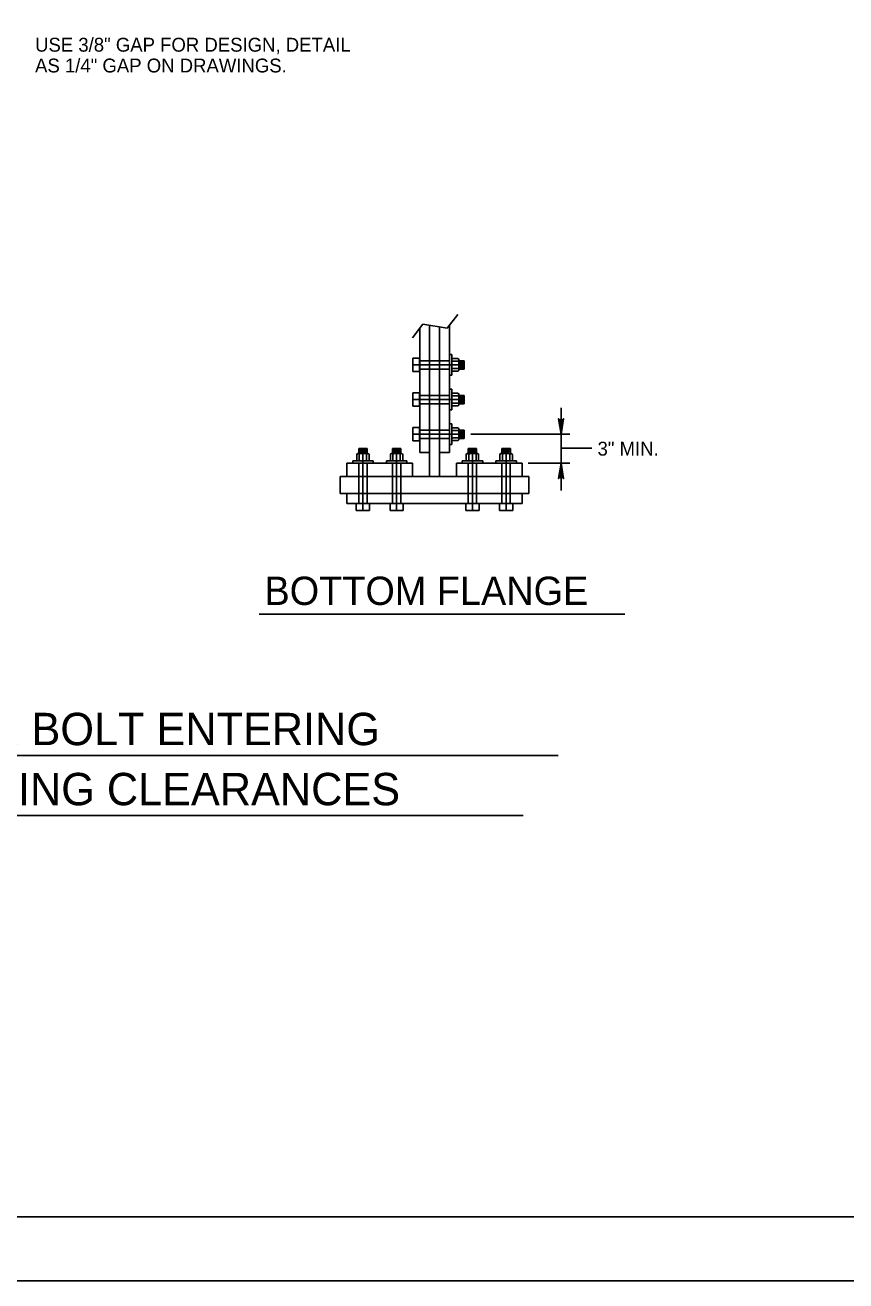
# Model space of a CAD drawing. Extents: x 638466 to 639375, y 297808 to 298996.
# Drawn here: x 638651.7 to 638843.6, y 297808.5 to 298101.9 of the extents above; entities that cross this region are included whole.
import ezdxf

# ---------------------------------------------------------------- set-up
doc = ezdxf.new("R2010")
doc.units = 0
for name, color, linetype in [('1', 7, 'Continuous'), ('2', 7, 'Continuous'), ('4', 7, 'Continuous'), ('PLT-BNDY', 7, 'Continuous')]:
    doc.layers.add(name, color=color, linetype=linetype)

msp = doc.modelspace()

# ---------------------------------------------------------------- linework, layer by layer
at = {"layer": '1'}
for p, q in [((638750.89, 298024.88), (638750.89, 298020.09)), ((638751.43, 298024.88), (638750.89, 298024.88)), ((638751.43, 298024.88), (638751.43, 298020.09)), ((638742.32, 298020.94), (638742.32, 298024.03)), ((638743.93, 298024.03), (638742.32, 298024.03)), ((638742.32, 298022.48), (638754.06, 298022.48)), ((638743.93, 298020.94), (638743.93, 298024.03)), ((638743.94, 298023.46), (638750.89, 298023.46)), ((638752.84, 298023.94), (638751.43, 298023.94)), ((638752.84, 298023.35), (638751.43, 298023.35)), ((638753.11, 298023.7), (638753.11, 298021.27)), ((638754.31, 298023.46), (638753.11, 298023.46)), ((638753.38, 298023.23), (638753.38, 298021.74)), ((638753.65, 298023.46), (638753.65, 298021.5)), ((638753.92, 298023.23), (638753.92, 298021.74)), ((638754.19, 298023.46), (638754.19, 298021.5)), ((638754.31, 298023.46), (638754.31, 298021.5)), ((638743.93, 298020.94), (638742.32, 298020.94)), ((638743.94, 298021.5), (638750.89, 298021.5)), ((638751.43, 298020.09), (638750.89, 298020.09)), ((638752.84, 298021.62), (638751.43, 298021.62)), ((638752.84, 298021.03), (638751.43, 298021.03)), ((638754.31, 298021.5), (638753.11, 298021.5)), ((638750.89, 298016.78), (638750.89, 298011.99)), ((638751.43, 298016.78), (638750.89, 298016.78)), ((638751.43, 298016.78), (638751.43, 298011.99)), ((638742.32, 298012.84), (638742.32, 298015.93)), ((638743.93, 298015.93), (638742.32, 298015.93)), ((638742.32, 298014.38), (638754.06, 298014.38)), ((638743.93, 298012.84), (638743.93, 298015.93)), ((638743.94, 298015.36), (638750.89, 298015.36)), ((638743.94, 298013.4), (638750.89, 298013.4)), ((638752.84, 298015.84), (638751.43, 298015.84)), ((638752.84, 298015.25), (638751.43, 298015.25)), ((638752.84, 298013.52), (638751.43, 298013.52)), ((638753.11, 298015.6), (638753.11, 298013.17)), ((638754.31, 298015.36), (638753.11, 298015.36)), ((638754.31, 298013.4), (638753.11, 298013.4)), ((638753.38, 298015.13), (638753.38, 298013.64)), ((638753.65, 298015.36), (638753.65, 298013.4)), ((638753.92, 298015.13), (638753.92, 298013.64)), ((638754.19, 298015.36), (638754.19, 298013.4)), ((638754.31, 298015.36), (638754.31, 298013.4)), ((638743.93, 298012.84), (638742.32, 298012.84)), ((638751.43, 298011.99), (638750.89, 298011.99)), ((638752.84, 298012.93), (638751.43, 298012.93)), ((638742.32, 298004.74), (638742.32, 298007.83)), ((638743.93, 298007.83), (638742.32, 298007.83)), ((638743.93, 298004.74), (638743.93, 298007.83)), ((638750.89, 298008.68), (638750.89, 298003.89)), ((638751.43, 298008.68), (638750.89, 298008.68)), ((638751.43, 298008.68), (638751.43, 298003.89)), ((638752.84, 298007.74), (638751.43, 298007.74)), ((638753.11, 298007.5), (638753.11, 298005.07)), ((638742.32, 298006.28), (638754.06, 298006.28)), ((638743.93, 298004.74), (638742.32, 298004.74)), ((638743.94, 298007.26), (638750.89, 298007.26)), ((638743.94, 298005.3), (638750.89, 298005.3)), ((638752.84, 298007.15), (638751.43, 298007.15)), ((638752.84, 298005.42), (638751.43, 298005.42)), ((638752.84, 298004.83), (638751.43, 298004.83)), ((638754.31, 298007.26), (638753.11, 298007.26)), ((638754.31, 298005.3), (638753.11, 298005.3)), ((638753.38, 298007.03), (638753.38, 298005.54)), ((638753.65, 298007.26), (638753.65, 298005.3)), ((638753.92, 298007.03), (638753.92, 298005.54)), ((638754.19, 298007.26), (638754.19, 298005.3)), ((638754.31, 298007.26), (638754.31, 298005.3)), ((638729.22, 298001.48), (638729.22, 298000.07)), ((638729.46, 298001.75), (638731.89, 298001.75)), ((638729.69, 298002.95), (638729.69, 298001.75)), ((638729.69, 298002.95), (638731.66, 298002.95)), ((638729.69, 298002.83), (638731.66, 298002.83)), ((638729.69, 298002.29), (638731.66, 298002.29)), ((638729.81, 298001.48), (638729.81, 298000.07)), ((638729.93, 298002.56), (638731.42, 298002.56)), ((638729.93, 298002.02), (638731.42, 298002.02)), ((638730.68, 297988.47), (638730.68, 298002.7)), ((638731.54, 298001.48), (638731.54, 298000.07)), ((638731.66, 298002.95), (638731.66, 298001.75)), ((638732.13, 298001.48), (638732.13, 298000.07)), ((638737.1, 298001.48), (638737.1, 298000.07)), ((638737.33, 298001.75), (638739.77, 298001.75)), ((638737.57, 298002.95), (638737.57, 298001.75)), ((638737.57, 298002.95), (638739.53, 298002.95)), ((638737.57, 298002.83), (638739.53, 298002.83)), ((638737.57, 298002.29), (638739.53, 298002.29)), ((638737.69, 298001.48), (638737.69, 298000.07)), ((638737.8, 298002.56), (638739.3, 298002.56)), ((638737.8, 298002.02), (638739.3, 298002.02)), ((638738.55, 297988.47), (638738.55, 298002.7)), ((638739.41, 298001.48), (638739.41, 298000.07)), ((638739.53, 298002.95), (638739.53, 298001.75)), ((638740, 298001.48), (638740, 298000.07)), ((638751.43, 298003.89), (638750.89, 298003.89)), ((638754.82, 298001.48), (638754.82, 298000.07)), ((638755.05, 298001.75), (638757.49, 298001.75)), ((638755.29, 298002.95), (638755.29, 298001.75)), ((638755.29, 298002.95), (638757.25, 298002.95)), ((638755.29, 298002.83), (638757.25, 298002.83)), ((638755.29, 298002.29), (638757.25, 298002.29)), ((638755.41, 298001.48), (638755.41, 298000.07)), ((638755.53, 298002.56), (638757.02, 298002.56)), ((638755.53, 298002.02), (638757.02, 298002.02)), ((638756.27, 297988.47), (638756.27, 298002.7)), ((638757.14, 298001.48), (638757.14, 298000.07)), ((638757.25, 298002.95), (638757.25, 298001.75)), ((638757.72, 298001.48), (638757.72, 298000.07)), ((638762.69, 298001.48), (638762.69, 298000.07)), ((638762.93, 298001.75), (638765.36, 298001.75)), ((638763.17, 298002.95), (638763.17, 298001.75)), ((638763.17, 298002.95), (638765.13, 298002.95)), ((638763.17, 298002.83), (638765.13, 298002.83)), ((638763.17, 298002.29), (638765.13, 298002.29)), ((638763.28, 298001.48), (638763.28, 298000.07)), ((638763.4, 298002.56), (638764.89, 298002.56)), ((638763.4, 298002.02), (638764.89, 298002.02)), ((638764.15, 297988.47), (638764.15, 298002.7)), ((638765.01, 298001.48), (638765.01, 298000.07)), ((638765.13, 298002.95), (638765.13, 298001.75)), ((638765.6, 298001.48), (638765.6, 298000.07)), ((638728.28, 298000.07), (638733.07, 298000.07)), ((638728.28, 298000.07), (638728.28, 297999.53)), ((638728.28, 297999.53), (638733.07, 297999.53)), ((638729.7, 297990.08), (638729.7, 297999.53)), ((638731.65, 297990.08), (638731.65, 297999.53)), ((638733.07, 298000.07), (638733.07, 297999.53)), ((638736.16, 298000.07), (638740.95, 298000.07)), ((638736.16, 298000.07), (638736.16, 297999.53)), ((638736.16, 297999.53), (638740.95, 297999.53)), ((638737.57, 297990.08), (638737.57, 297999.53)), ((638739.53, 297990.08), (638739.53, 297999.53)), ((638740.95, 298000.07), (638740.95, 297999.53)), ((638753.88, 298000.07), (638758.67, 298000.07)), ((638753.88, 298000.07), (638753.88, 297999.53)), ((638753.88, 297999.53), (638758.67, 297999.53)), ((638755.29, 297990.08), (638755.29, 297999.53)), ((638757.25, 297990.08), (638757.25, 297999.53)), ((638758.67, 298000.07), (638758.67, 297999.53)), ((638761.75, 298000.07), (638766.54, 298000.07)), ((638761.75, 298000.07), (638761.75, 297999.53)), ((638761.75, 297999.53), (638766.54, 297999.53)), ((638763.17, 297990.08), (638763.17, 297999.53)), ((638765.12, 297990.08), (638765.12, 297999.53)), ((638766.54, 298000.07), (638766.54, 297999.53)), ((638732.22, 297990.08), (638729.13, 297990.08)), ((638729.13, 297990.08), (638729.13, 297988.47)), ((638732.22, 297990.08), (638732.22, 297988.47)), ((638740.09, 297990.08), (638737.01, 297990.08)), ((638737.01, 297990.08), (638737.01, 297988.47)), ((638740.09, 297990.08), (638740.09, 297988.47)), ((638757.81, 297990.08), (638754.73, 297990.08)), ((638754.73, 297990.08), (638754.73, 297988.47)), ((638757.81, 297990.08), (638757.81, 297988.47)), ((638765.69, 297990.08), (638762.6, 297990.08)), ((638762.6, 297990.08), (638762.6, 297988.47)), ((638765.69, 297990.08), (638765.69, 297988.47)), ((638732.22, 297988.47), (638729.13, 297988.47)), ((638740.09, 297988.47), (638737.01, 297988.47)), ((638757.81, 297988.47), (638754.73, 297988.47)), ((638765.69, 297988.47), (638762.6, 297988.47)), ((638505.96, 297823.46), (639291.96, 297823.46))]:
    msp.add_line(p, q, dxfattribs=at)
for points in [[(638776.57, 298009.71), (638776.82, 298009.59), (638777, 298006.28), (638776.57, 298009.71), (638776.42, 298009.89), (638777, 298006.28), (638777.17, 298009.58), (638777.41, 298009.7), (638777, 298006.28), (638777.58, 298009.89), (638777.41, 298009.7)], [(638776.58, 297996.1), (638776.82, 297996.22), (638777.01, 297999.53), (638776.58, 297996.1), (638776.42, 297995.92), (638777.01, 297999.53), (638777.17, 297996.23), (638777.42, 297996.11), (638777.01, 297999.53), (638777.58, 297995.92), (638777.42, 297996.11)]]:
    msp.add_lwpolyline(points, dxfattribs=at)
for centre, major_axis, start_param, end_param in [((638752.84, 298023.7), (0.269, 0), 0, 1.570796), ((638752.84, 298023.58), (-0.269, 0), 1.570796, 3.141593), ((638752.84, 298023.11), (0.269, 0), 0, 1.570796), ((638752.84, 298021.85), (-0.269, 0), 1.570796, 3.141593), ((638752.84, 298021.38), (0.269, 0), 0, 1.570796), ((638752.84, 298021.27), (-0.269, 0), 1.570796, 3.141593), ((638752.84, 298015.6), (0.269, 0), 0, 1.570796), ((638752.84, 298015.48), (-0.269, 0), 1.570796, 3.141593), ((638752.84, 298015.01), (0.269, 0), 0, 1.570796), ((638752.84, 298013.75), (-0.269, 0), 1.570796, 3.141593), ((638752.84, 298013.28), (0.269, 0), 0, 1.570796), ((638752.84, 298013.17), (-0.269, 0), 1.570796, 3.141593), ((638752.84, 298007.5), (0.269, 0), 0, 1.570796), ((638752.84, 298007.38), (-0.269, 0), 1.570796, 3.141593), ((638752.84, 298006.91), (0.269, 0), 0, 1.570796), ((638752.84, 298005.65), (-0.269, 0), 1.570796, 3.141593), ((638752.84, 298005.18), (0.269, 0), 0, 1.570796), ((638752.84, 298005.07), (-0.269, 0), 1.570796, 3.141593), ((638729.46, 298001.48), (0, 0.269), 0, 1.570796), ((638729.58, 298001.48), (0, -0.269), 1.570796, 3.141593), ((638730.05, 298001.48), (0, 0.269), 0, 1.570796), ((638731.3, 298001.48), (0, -0.269), 1.570796, 3.141593), ((638731.78, 298001.48), (0, 0.269), 0, 1.570796), ((638731.89, 298001.48), (0, -0.269), 1.570796, 3.141593), ((638737.33, 298001.48), (0, 0.269), 0, 1.570796), ((638737.45, 298001.48), (0, -0.269), 1.570796, 3.141593), ((638737.92, 298001.48), (0, 0.269), 0, 1.570796), ((638739.18, 298001.48), (0, -0.269), 1.570796, 3.141593), ((638739.65, 298001.48), (0, 0.269), 0, 1.570796), ((638739.77, 298001.48), (0, -0.269), 1.570796, 3.141593), ((638755.05, 298001.48), (0, 0.269), 0, 1.570796), ((638755.17, 298001.48), (0, -0.269), 1.570796, 3.141593), ((638755.64, 298001.48), (0, 0.269), 0, 1.570796), ((638756.9, 298001.48), (0, -0.269), 1.570796, 3.141593), ((638757.37, 298001.48), (0, 0.269), 0, 1.570796), ((638757.49, 298001.48), (0, -0.269), 1.570796, 3.141593), ((638762.93, 298001.48), (0, 0.269), 0, 1.570796), ((638763.05, 298001.48), (0, -0.269), 1.570796, 3.141593), ((638763.52, 298001.48), (0, 0.269), 0, 1.570796), ((638764.77, 298001.48), (0, -0.269), 1.570796, 3.141593), ((638765.25, 298001.48), (0, 0.269), 0, 1.570796), ((638765.36, 298001.48), (0, -0.269), 1.570796, 3.141593)]:
    msp.add_ellipse(centre, major_axis=major_axis, ratio=0.875, start_param=start_param, end_param=end_param, dxfattribs=at)
at = {"layer": '2'}
for p, q in [((638750.37, 298031.09), (638752.83, 298034.29)), ((638742.24, 298028.77), (638744.7, 298031.98)), ((638743.94, 298001.99), (638743.94, 298030.98)), ((638744.7, 298031.98), (638750.37, 298031.09)), ((638746.23, 297996.39), (638746.23, 298031.74)), ((638748.59, 297996.39), (638748.59, 298031.37)), ((638750.89, 298001.99), (638750.89, 298031.76)), ((638746.23, 298001.99), (638743.94, 298001.99)), ((638750.89, 298001.99), (638748.59, 298001.99)), ((638726.94, 297999.53), (638742.29, 297999.53)), ((638726.94, 297999.53), (638726.94, 297996.39)), ((638742.29, 297999.53), (638742.29, 297996.39)), ((638752.53, 297999.53), (638752.53, 297996.39)), ((638767.89, 297999.53), (638752.53, 297999.53)), ((638767.89, 297999.53), (638767.89, 297996.39)), ((638725.36, 297996.39), (638725.36, 297992.45)), ((638748.6, 297996.39), (638725.36, 297996.39)), ((638748.59, 297996.39), (638769.46, 297996.39)), ((638769.46, 297996.39), (638769.46, 297992.45)), ((638725.36, 297992.45), (638769.46, 297992.45)), ((638726.94, 297992.45), (638726.94, 297990.08)), ((638726.94, 297990.08), (638767.89, 297990.08)), ((638767.89, 297990.08), (638767.89, 297992.45))]:
    msp.add_line(p, q, dxfattribs=at)
at = {"layer": '4'}
for p, q in [((638777, 298012.47), (638777.01, 297993.12)), ((638755.93, 298006.28), (638779.01, 298006.28)), ((638777, 298003.03), (638784.17, 298003.03)), ((638769.33, 297999.53), (638779.01, 297999.53)), ((638791.86, 297964.25), (638706.41, 297964.25)), ((638776.33, 297931.2), (638573.64, 297931.2)), ((638768.09, 297917.23), (638579.72, 297917.23))]:
    msp.add_line(p, q, dxfattribs=at)
at = {"layer": 'PLT-BNDY'}
msp.add_lwpolyline([(638465.96, 298402.46), (639306.96, 298402.46), (639306.96, 297808.46), (638465.96, 297808.46)], close=True, dxfattribs=at)

# ---------------------------------------------------------------- texts
at = {"layer": '4'}
for s, height, p in [('USE 3/8" GAP FOR DESIGN, DETAIL', 3.24, (638654.04, 298095.67)), ('AS 1/4" GAP ON DRAWINGS.', 3.24, (638654.04, 298090.81)), ('3" MIN.', 3.24, (638785.51, 298001.29)), ('BOTTOM FLANGE', 6.615, (638707.66, 297966.39)), ('7/8" DIAMETER BOLT ENTERING', 7.56, (638577.71, 297933.63)), ('AND TIGHTENING CLEARANCES', 7.56, (638581.52, 297919.59))]:
    msp.add_text(s, height=height, dxfattribs=at).set_placement(p)

doc.saveas('drawing.dxf')
